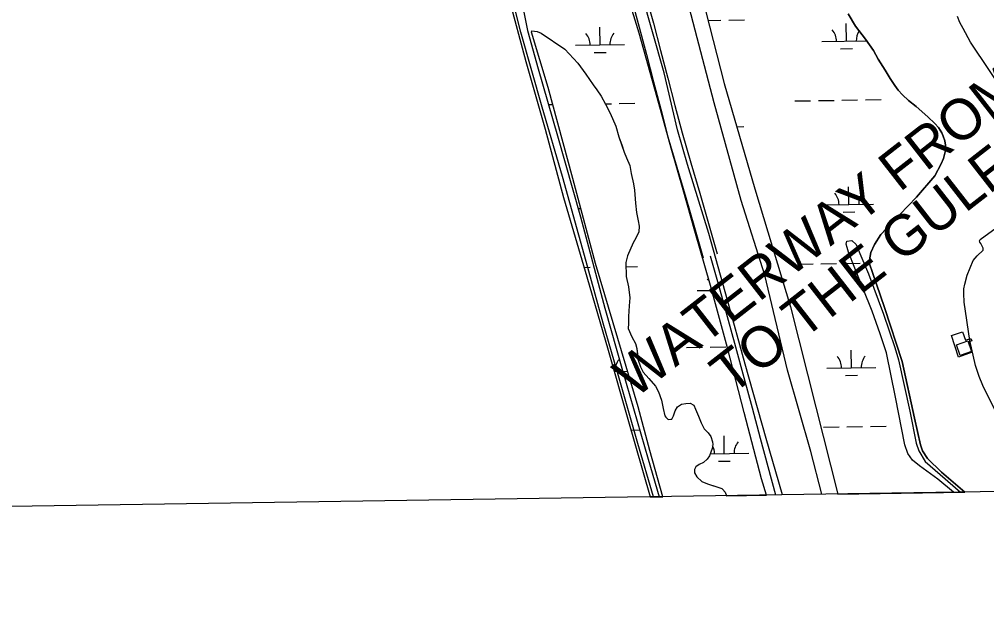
# Model space of a CAD drawing. Extents: x 3812694 to 3850888, y 319753 to 345638.
# Drawn here: x 3829488 to 3831459, y 325178 to 326361 of the extents above; entities that cross this region are included whole.
import ezdxf

# ---------------------------------------------------------------- set-up
doc = ezdxf.new("R2010")
doc.units = 0
for name, color, linetype in [('V-BLDG-OTLN', 7, 'Continuous'), ('V-CHAN-DOCK', 7, 'Continuous'), ('V-GRID-FRAM', 7, 'Continuous'), ('V-LEVE-TOET', 7, 'Continuous'), ('V-RIVR-IDEN', 7, 'Continuous'), ('V-RIVR-JETY', 7, 'Continuous'), ('V-ROAD-CNTR', 7, 'Continuous'), ('V-TOPO-SHOR', 7, 'Continuous'), ('V-WETL-SWMP', 7, 'Continuous')]:
    doc.layers.add(name, color=color, linetype=linetype)

msp = doc.modelspace()

# ---------------------------------------------------------------- linework, layer by layer
at = {"layer": 'V-BLDG-OTLN'}
msp.add_lwpolyline([(3831397.8, 325697.6), (3831420.7, 325705.5), (3831428.2, 325684), (3831405.2, 325676)], close=True, dxfattribs=at)
at = {"layer": 'V-CHAN-DOCK'}
msp.add_lwpolyline([(3831428.4, 325705.6), (3831422, 325703.6), (3831429.3, 325682.4), (3831401.7, 325672.7), (3831387.2, 325716.7), (3831409.8, 325724.1), (3831415.5, 325706.9), (3831426.8, 325710.6), (3831428.4, 325705.6)], dxfattribs=at)
at = {"layer": 'V-GRID-FRAM'}
msp.add_lwpolyline([(3816670, 343358.9), (3848499.3, 343840.5), (3848782.3, 325660.2), (3816937.1, 325178.5), (3816670, 343358.9)], dxfattribs=at)
at = {"layer": 'V-LEVE-TOET'}
for points in [[(3831042.8, 325391.9), (3831009.9, 325506.7), (3830966.8, 325658.5), (3830930.7, 325788.6), (3830892.9, 325924.7), (3830849.6, 326065), (3830829.1, 326135.4), (3830801.8, 326251.8), (3830755.5, 326414.6)], [(3831122.9, 325393.1), (3831100.7, 325480.4), (3831053.1, 325646.3), (3831007.2, 325839.4), (3830959, 325991.9), (3830904, 326190.5), (3830849.7, 326398.1)]]:
    msp.add_lwpolyline(points, dxfattribs=at)
at = {"layer": 'V-RIVR-JETY'}
for points in [[(3830779.9, 325387.9), (3830748, 325496.7), (3830711.5, 325624.7), (3830677.4, 325741.7), (3830643.2, 325867.5), (3830594.5, 326040.4), (3830553.4, 326182.1), (3830510.1, 326334.7), (3830481.5, 326448.5)], [(3830504.6, 326433.2), (3830523.7, 326338.2), (3830545.2, 326259.8), (3830584.7, 326123.7), (3830631.1, 325958.2), (3830680.8, 325772), (3830716.8, 325645), (3830769.4, 325464.8), (3830791.6, 325388.1)], [(3831391.1, 325397.2), (3831359.7, 325424.1), (3831322.3, 325451.3), (3831308, 325462.6), (3831298.4, 325475.9), (3831292.3, 325493.6), (3831273.5, 325590.8), (3831254.8, 325681.2), (3831241.7, 325719.7), (3831225.9, 325766.1), (3831190.6, 325854), (3831177.6, 325886.2), (3831174.4, 325896), (3831172.7, 325902.7), (3831173.8, 325908.6), (3831184.5, 325910.3), (3831193.2, 325901.7), (3831200.5, 325883.7), (3831217.9, 325842.1), (3831248.4, 325760), (3831272, 325692.5), (3831279, 325666.9), (3831302.2, 325562.7), (3831315.1, 325497), (3831320.4, 325481.7), (3831333.7, 325460.1), (3831364.3, 325433.3), (3831405.9, 325397.4)]]:
    msp.add_lwpolyline(points, dxfattribs=at)
at = {"layer": 'V-ROAD-CNTR'}
for points in [[(3830764.7, 326408.6), (3830779.8, 326352.8), (3830794.6, 326296.9), (3830809.3, 326241), (3830823.9, 326185.1), (3830838.2, 326129.4), (3830856.4, 326068.1), (3830874.5, 326006.4), (3830892.4, 325944.7), (3830910.1, 325883)], [(3830735.8, 326400.7), (3830750.8, 326345), (3830765.6, 326289.2), (3830780.3, 326233.4), (3830794.8, 326177.6), (3830809.3, 326121.4), (3830827.6, 326059.6), (3830845.7, 325998), (3830863.5, 325936.4), (3830881.2, 325874.7)], [(3830895.6, 325878.9), (3830913.1, 325817.1), (3830930.4, 325755.3), (3830947.4, 325693.4), (3830964.3, 325631.4), (3830981, 325569.4), (3830997.4, 325507.4), (3831029, 325391.7)]]:
    msp.add_lwpolyline(points, dxfattribs=at)
at = {"layer": 'V-TOPO-SHOR'}
for points in [[(3830485.5, 326404.2), (3830520, 326275.1), (3830559.3, 326137.1), (3830596.9, 325998), (3830644.2, 325835.9), (3830687.8, 325686.8), (3830727.8, 325546.5), (3830773.1, 325387.8)], [(3831176.5, 326371.6), (3831191.6, 326346.9), (3831212.1, 326320.5), (3831228.3, 326297), (3831238, 326279.9), (3831252.4, 326256.9), (3831262.1, 326240.5), (3831271.7, 326225.8), (3831278.9, 326216.4), (3831287.3, 326207), (3831299.9, 326195.3), (3831315.4, 326183), (3831338.8, 326161.9), (3831353.1, 326148.4), (3831360.9, 326140.2), (3831367.6, 326129.6), (3831370.6, 326122.6), (3831373.7, 326113.1), (3831375, 326104.3), (3831375.1, 326093.6), (3831371.1, 326077), (3831366.5, 326066.2), (3831353.1, 326041.8), (3831316.3, 325998.2), (3831264.7, 325945.5), (3831243.6, 325922.1), (3831230.2, 325901.8), (3831222.7, 325885.8), (3831220.5, 325870.9), (3831220, 325862.6), (3831226.1, 325844.9), (3831250.6, 325773.5), (3831286.7, 325663.7), (3831311.7, 325547.9), (3831324.1, 325494.1), (3831328.4, 325481.7), (3831338.1, 325465.8), (3831366.8, 325438.3), (3831414.5, 325397.5)], [(3831503.1, 326198.7), (3831426, 326313.9), (3831410.9, 326342.2), (3831404.2, 326354.6), (3831399.4, 326366.4)], [(3830799, 325388.2), (3830772.9, 325482.4), (3830748.9, 325571.4), (3830707.2, 325710.5), (3830661.8, 325863.2), (3830616.1, 326036.5), (3830565.6, 326221.6), (3830531.3, 326334.8), (3830532.5, 326337.2), (3830543.1, 326336.1), (3830551.4, 326332.6), (3830599.7, 326300), (3830626, 326271.4), (3830642.2, 326249.1), (3830657.2, 326227.3), (3830665, 326217.4), (3830673.4, 326204.5), (3830682.5, 326188), (3830691.6, 326169.8), (3830703.7, 326143.3), (3830709.8, 326121.5), (3830715.3, 326105), (3830720.2, 326090.3), (3830725.1, 326078.5), (3830731.7, 326063.2), (3830734.9, 326046.7), (3830739.2, 326025.4), (3830741.2, 326013), (3830743.8, 325986.5), (3830745.2, 325967.5), (3830748.9, 325950.4), (3830750.8, 325939.2), (3830750.4, 325928), (3830744, 325914.9), (3830738.8, 325905.4), (3830727.2, 325879.2), (3830723.8, 325865.6), (3830724.7, 325836.6), (3830729.1, 325816), (3830731.7, 325793.6), (3830730.7, 325777), (3830729.2, 325755.1), (3830729.3, 325740.9), (3830728.3, 325730.8), (3830733.1, 325720.3), (3830736.1, 325713.8), (3830743.4, 325700.3), (3830746.4, 325690.2), (3830747.2, 325678.4), (3830747.9, 325668.4), (3830753.4, 325652.5), (3830759.4, 325641.9), (3830770.8, 325629), (3830783.9, 325613.2), (3830790, 325602), (3830796.1, 325584.9), (3830799.8, 325567.8), (3830803.5, 325553.1), (3830805.3, 325550.2), (3830809.5, 325546.1), (3830810.7, 325545.5), (3830815.4, 325546.1), (3830817.2, 325546.1)], [(3831486.5, 325543.3), (3831450.8, 325614.5), (3831443.5, 325632.8), (3831436.1, 325655.3), (3831424.9, 325706.1), (3831413.4, 325784.8), (3831412.6, 325802.5), (3831412.5, 325812), (3831414.2, 325821.5), (3831419.3, 325839.3), (3831431.4, 325869.1), (3831439.6, 325878.6), (3831451.9, 325890.6), (3831451.9, 325894.2), (3831447, 325904.2), (3831445.2, 325906.6), (3831444.6, 325909.5), (3831445.8, 325912.5), (3831523.3, 325968.4)], [(3830817.2, 325546.1), (3830818.4, 325547.3), (3830821.2, 325553.3), (3830824.1, 325563.4), (3830829.3, 325571.1), (3830837, 325576.5), (3830845.8, 325578.4), (3830854.7, 325578.5), (3830862.4, 325574.4), (3830866, 325566.8), (3830871.5, 325552.1), (3830877, 325538.5), (3830883.6, 325526.8), (3830891.4, 325518.6), (3830896.8, 325510.9), (3830900.5, 325499.7), (3830901.1, 325494.4), (3830899.4, 325486.1), (3830894.3, 325471.3), (3830889.6, 325464.7), (3830882, 325457.6), (3830873.2, 325453.9), (3830866.1, 325449.1), (3830863.8, 325443.8), (3830863.9, 325436.7), (3830868.1, 325429), (3830878.9, 325419.1), (3830890.2, 325414.5), (3830907.4, 325408.8), (3830919.2, 325404.8), (3830921, 325403.6), (3830926.4, 325397.7), (3830928.7, 325390.2)]]:
    msp.add_lwpolyline(points, dxfattribs=at)
at = {"layer": 'V-WETL-SWMP'}
for p, q in [((3830853.8, 326506.8), (3830924, 326230.3)), ((3830750.7, 326332.6), (3830720.5, 326430.6)), ((3830485.5, 326404.2), (3830520, 326275.1)), ((3831191.6, 326346.9), (3831176.5, 326371.6)), ((3830671.3, 326308.6), (3830670.8, 326344.6)), ((3830891.5, 326358.4), (3830917.6, 326358.8)), ((3830933.6, 326359), (3830965.6, 326359.5)), ((3831173.2, 326316.2), (3831172.6, 326352.2)), ((3831212.1, 326320.5), (3831191.6, 326346.9)), ((3830531.3, 326334.8), (3830532.5, 326337.2)), ((3830565.6, 326221.6), (3830531.3, 326334.8)), ((3830532.5, 326337.2), (3830543.1, 326336.1)), ((3830543.1, 326336.1), (3830551.4, 326332.6)), ((3830551.4, 326332.6), (3830599.7, 326300)), ((3830787.9, 326201.3), (3830750.7, 326332.6)), ((3830621.3, 326307.9), (3830721.3, 326309.4)), ((3831123.2, 326315.5), (3831214.6, 326316.8)), ((3831228.3, 326297), (3831212.1, 326320.5)), ((3830599.7, 326300), (3830626, 326271.4)), ((3830659.5, 326293), (3830683.5, 326293.4)), ((3831161.4, 326300.6), (3831185.4, 326301)), ((3831238, 326279.9), (3831228.3, 326297)), ((3830520, 326275.1), (3830559.3, 326137.1)), ((3830626, 326271.4), (3830642.2, 326249.1)), ((3831252.4, 326256.9), (3831238, 326279.9)), ((3830642.2, 326249.1), (3830657.2, 326227.3)), ((3831262.1, 326240.5), (3831252.4, 326256.9)), ((3830657.2, 326227.3), (3830665, 326217.4)), ((3830924, 326230.3), (3830986.3, 326015.3)), ((3831271.7, 326225.8), (3831262.1, 326240.5)), ((3831278.9, 326216.4), (3831271.7, 326225.8)), ((3830616.1, 326036.5), (3830565.6, 326221.6)), ((3830665, 326217.4), (3830673.4, 326204.5)), ((3831287.3, 326207), (3831278.9, 326216.4)), ((3831299.9, 326195.3), (3831287.3, 326207)), ((3830566.3, 326186.9), (3830575.1, 326187.1)), ((3830673.4, 326204.5), (3830682.5, 326188)), ((3830682.1, 326188.7), (3830694.3, 326188.9)), ((3830682.5, 326188), (3830691.6, 326169.8)), ((3830710.3, 326189.1), (3830742.3, 326189.6)), ((3830816.3, 326098.2), (3830787.9, 326201.3)), ((3831068.1, 326194.5), (3831100.1, 326195)), ((3831116.1, 326195.3), (3831148.1, 326195.7)), ((3831164.1, 326196), (3831196.1, 326196.5)), ((3831212.1, 326196.7), (3831244.1, 326197.2)), ((3831315.4, 326183), (3831299.9, 326195.3)), ((3830691.6, 326169.8), (3830703.7, 326143.3)), ((3831338.8, 326161.9), (3831315.4, 326183)), ((3831353.1, 326148.4), (3831338.8, 326161.9)), ((3831360.9, 326140.2), (3831353.1, 326148.4)), ((3830559.3, 326137.1), (3830596.9, 325998)), ((3830703.7, 326143.3), (3830709.8, 326121.5)), ((3830949.6, 326142), (3830964.3, 326142.2)), ((3831367.6, 326129.6), (3831360.9, 326140.2)), ((3831370.6, 326122.6), (3831367.6, 326129.6)), ((3830709.8, 326121.5), (3830720.2, 326090.3)), ((3831373.7, 326113.1), (3831370.6, 326122.6)), ((3831374.9, 326104.3), (3831373.7, 326113.1)), ((3830720.2, 326090.3), (3830725.1, 326078.5)), ((3830840.7, 326013.3), (3830816.3, 326098.2)), ((3831371.1, 326077), (3831375.1, 326093.6)), ((3831375.1, 326093.6), (3831374.9, 326104.3)), ((3830725.1, 326078.5), (3830731.7, 326063.2)), ((3831366.5, 326066.2), (3831371.1, 326077)), ((3830731.7, 326063.2), (3830734.9, 326046.7)), ((3831353.1, 326041.8), (3831366.5, 326066.2)), ((3830661.8, 325863.2), (3830616.1, 326036.5)), ((3830734.9, 326046.7), (3830739.2, 326025.4)), ((3831316.3, 325998.2), (3831353.1, 326041.8)), ((3831344.5, 326032.5), (3831345.3, 326032.5)), ((3830739.2, 326025.4), (3830741.2, 326013)), ((3830741.2, 326013), (3830743.8, 325986.5)), ((3830864.2, 325929.4), (3830840.7, 326013.3)), ((3830986.3, 326015.3), (3831059.2, 325775.2)), ((3831178.2, 325983.6), (3831177.6, 326019.6)), ((3830596.9, 325998), (3830644.2, 325835.9)), ((3831264.7, 325945.5), (3831316.3, 325998.2)), ((3830626.3, 325975.2), (3830632.2, 325975.3)), ((3830743.8, 325986.5), (3830745.2, 325967.5)), ((3831128.2, 325982.8), (3831228.2, 325984.3)), ((3830745.2, 325967.5), (3830748.9, 325950.4)), ((3830748.9, 325950.4), (3830750.8, 325939.2)), ((3831166.4, 325968), (3831190.4, 325968.3)), ((3830750.8, 325939.2), (3830750.4, 325928)), ((3830896, 325818.7), (3830864.2, 325929.4)), ((3831243.6, 325922.1), (3831264.7, 325945.5)), ((3830744, 325914.9), (3830738.8, 325905.4)), ((3830750.4, 325928), (3830744, 325914.9)), ((3831230.2, 325901.8), (3831243.6, 325922.1)), ((3830738.8, 325905.4), (3830727.2, 325879.2)), ((3831222.7, 325885.8), (3831230.2, 325901.8)), ((3830727.2, 325879.2), (3830723.8, 325865.6)), ((3831220, 325862.6), (3831220.5, 325870.9)), ((3831220.5, 325870.9), (3831222.7, 325885.8)), ((3830638.5, 325855.3), (3830651.3, 325855.5)), ((3830707.2, 325710.5), (3830661.8, 325863.2)), ((3830723.8, 325865.6), (3830724.7, 325836.6)), ((3830724.1, 325856.6), (3830747.3, 325857)), ((3831073.2, 325861.9), (3831105.2, 325862.4)), ((3831121.2, 325862.6), (3831153.2, 325863.1)), ((3831169.2, 325863.4), (3831201.2, 325863.8)), ((3831217.2, 325864.1), (3831220.1, 325864.1)), ((3831226.1, 325844.9), (3831220, 325862.6)), ((3830644.2, 325835.9), (3830687.8, 325686.8)), ((3830724.7, 325836.6), (3830729.1, 325816)), ((3831250.6, 325773.5), (3831226.1, 325844.9)), ((3830729.1, 325816), (3830731.7, 325793.6)), ((3830931.2, 325691.2), (3830896, 325818.7)), ((3830731.7, 325793.6), (3830730.7, 325777)), ((3830869.4, 325808.1), (3830898.8, 325808.5)), ((3830730.7, 325777), (3830729.2, 325755.1)), ((3831059.2, 325775.2), (3831111.2, 325570.4)), ((3831286.7, 325663.7), (3831250.6, 325773.5)), ((3830729.2, 325755.1), (3830729.3, 325740.9)), ((3830729.3, 325740.9), (3830728.3, 325730.8)), ((3830728.3, 325730.8), (3830736.1, 325713.8)), ((3830736.1, 325713.8), (3830743.4, 325700.3)), ((3830748.9, 325571.4), (3830707.2, 325710.5)), ((3830743.4, 325700.3), (3830746.4, 325690.2)), ((3830895.7, 325693), (3830927.7, 325693.5)), ((3830687.8, 325686.8), (3830727.8, 325546.5)), ((3830746.4, 325690.2), (3830747.9, 325668.4)), ((3830847.7, 325692.3), (3830879.7, 325692.8)), ((3830965.1, 325559.8), (3830931.2, 325691.2)), ((3831183.2, 325650.9), (3831182.7, 325686.9)), ((3830747.9, 325668.4), (3830753.4, 325652.5)), ((3831311.7, 325547.9), (3831286.7, 325663.7)), ((3830700.1, 325643.6), (3830727.1, 325644)), ((3830753.4, 325652.5), (3830759.4, 325641.9)), ((3830759.4, 325641.9), (3830770.8, 325629)), ((3831133.2, 325650.2), (3831233.2, 325651.7)), ((3831171.5, 325635.3), (3831195.5, 325635.7)), ((3830770.8, 325629), (3830783.9, 325613.2)), ((3830783.9, 325613.2), (3830790, 325602)), ((3830790, 325602), (3830796.1, 325584.9)), ((3830796.1, 325584.9), (3830799.8, 325567.8)), ((3830829.3, 325571.1), (3830837, 325576.5)), ((3830837, 325576.5), (3830845.8, 325578.4)), ((3830845.8, 325578.4), (3830854.7, 325578.5)), ((3830854.7, 325578.5), (3830862.4, 325574.4)), ((3830772.9, 325482.4), (3830748.9, 325571.4)), ((3830799.8, 325567.8), (3830803.5, 325553.1)), ((3830821.2, 325553.3), (3830824.1, 325563.4)), ((3830824.1, 325563.4), (3830829.3, 325571.1)), ((3830862.4, 325574.4), (3830866, 325566.8)), ((3830866, 325566.8), (3830871.5, 325552.1)), ((3831000.4, 325424.8), (3830965.1, 325559.8)), ((3831111.2, 325570.4), (3831155.4, 325393.6)), ((3830727.8, 325546.5), (3830773.1, 325387.8)), ((3830803.5, 325553.1), (3830805.3, 325550.2)), ((3830805.3, 325550.2), (3830809.5, 325546.1)), ((3830809.5, 325546.1), (3830810.7, 325545.5)), ((3830810.7, 325545.5), (3830815.4, 325546.1)), ((3830815.4, 325546.1), (3830817.2, 325546.1)), ((3830817.2, 325546.1), (3830818.4, 325547.3)), ((3830818.4, 325547.3), (3830821.2, 325553.3)), ((3830871.5, 325552.1), (3830877, 325538.5)), ((3830877, 325538.5), (3830883.6, 325526.8)), ((3831324.1, 325494.1), (3831311.7, 325547.9)), ((3830734.2, 325524.1), (3830752.3, 325524.3)), ((3830883.6, 325526.8), (3830891.4, 325518.6)), ((3830891.4, 325518.6), (3830896.8, 325510.9)), ((3831126.2, 325530), (3831158.2, 325530.5)), ((3831174.2, 325530.7), (3831206.2, 325531.2)), ((3831222.2, 325531.4), (3831254.2, 325531.9)), ((3830896.8, 325510.9), (3830900.5, 325499.7)), ((3830900.5, 325499.7), (3830901.1, 325494.4)), ((3830924.4, 325476.2), (3830923.9, 325512.2)), ((3830799, 325388.2), (3830772.9, 325482.4)), ((3830899.4, 325486.1), (3830894.3, 325471.3)), ((3830895.8, 325475.8), (3830974.4, 325476.9)), ((3830901.1, 325494.4), (3830899.4, 325486.1)), ((3831328.4, 325481.7), (3831324.1, 325494.1)), ((3831338.1, 325465.8), (3831328.4, 325481.7)), ((3830882, 325457.6), (3830873.2, 325453.9)), ((3830889.6, 325464.7), (3830882, 325457.6)), ((3830894.3, 325471.3), (3830889.6, 325464.7)), ((3830912.6, 325460.6), (3830936.6, 325460.9)), ((3831366.8, 325438.3), (3831338.1, 325465.8)), ((3830866.1, 325449.1), (3830863.8, 325443.8)), ((3830863.8, 325443.8), (3830863.9, 325436.7)), ((3830863.9, 325436.7), (3830868.1, 325429)), ((3830873.2, 325453.9), (3830866.1, 325449.1)), ((3831414.5, 325397.5), (3831366.8, 325438.3)), ((3830868.1, 325429), (3830878.9, 325419.1)), ((3830878.9, 325419.1), (3830890.2, 325414.5)), ((3831010.3, 325391.4), (3831000.4, 325424.8)), ((3830890.2, 325414.5), (3830919.2, 325404.8)), ((3830919.2, 325404.8), (3830921, 325403.6)), ((3830921, 325403.6), (3830926.4, 325397.7)), ((3830926.4, 325397.7), (3830928.7, 325390.2)), ((3831155.4, 325393.6), (3831414.5, 325397.5)), ((3830773.1, 325387.8), (3830799, 325388.2)), ((3830928.7, 325390.2), (3831010.3, 325391.4))]:
    msp.add_line(p, q, dxfattribs=at)
for centre, start, end in [((3830616.1, 326308.3), 0.0949, 41.6385), ((3830726.5, 326309.9), 140.0949, 181.6385), ((3831117.9, 326315.8), 0.0949, 41.6385), ((3831228.4, 326317.5), 146.0754, 181.6385), ((3831123, 325983.2), 0.0949, 41.6385), ((3831233.4, 325984.9), 140.0949, 181.6385), ((3830864.1, 325808.5), 34.5012, 41.6385), ((3831128, 325650.6), 0.0949, 41.6385), ((3831238.5, 325652.2), 140.0949, 181.6385), ((3830736.6, 325644.7), 140.0949, 181.6385), ((3830979.6, 325477.5), 140.0949, 181.6385), ((3830869.2, 325475.8), 0.0949, 26.9262)]:
    msp.add_arc(centre, 35.2, start, end, dxfattribs=at)

# ---------------------------------------------------------------- texts
at = {"layer": 'V-RIVR-IDEN'}
for s, p in [('WATERWAY FROM EMPIRE LA.', (3830741.7, 325586.5)), ('TO THE GULF OF MEXICO', (3830938.5, 325593.3))]:
    msp.add_text(s, height=83, rotation=37.948, dxfattribs=at).set_placement(p)

doc.saveas('drawing.dxf')
